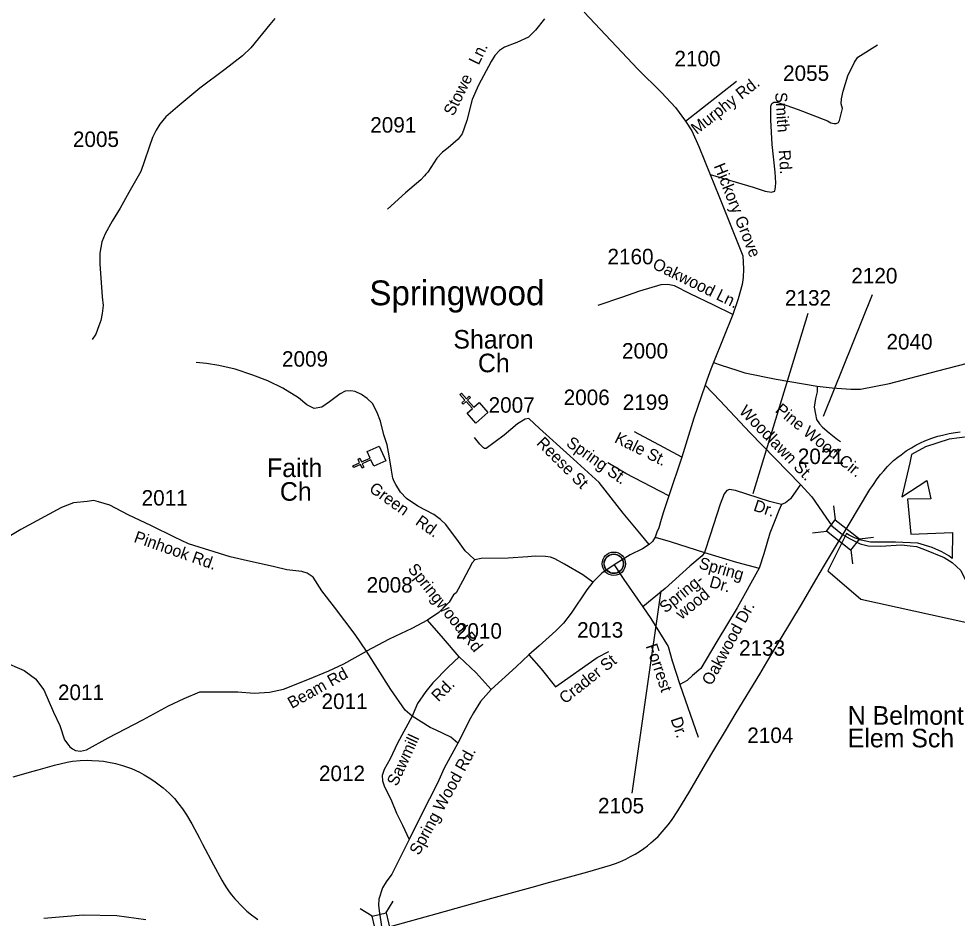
# Model space of a CAD drawing. Extents: x 1364363 to 1407445, y 538563 to 573342.
# Drawn here: x 1379893 to 1387464, y 558110 to 565370 of the extents above; entities that cross this region are included whole.
import ezdxf

# ---------------------------------------------------------------- set-up
doc = ezdxf.new("R2010")
doc.units = 0
for name, color, linetype in [('Exist Boundary Political City Limit New', 7, 'Continuous'), ('Exist Boundary Political City Limit New Hole', 7, 'Continuous'), ('Exist Civil Demographics Community CELL', 7, 'Continuous'), ('Exist Civil Demographics Community Label', 7, 'Continuous'), ('Exist Cultural Church CELL', 7, 'Continuous'), ('Exist Cultural Church Label', 7, 'Continuous'), ('Exist Cultural Educational Facility High Label', 7, 'Continuous'), ('Exist Railroad Mainline', 7, 'Continuous'), ('Exist Road Secondary Structure Standard Bridge CELL', 7, 'Continuous'), ('Exist Road Secondary Type 51 Attributed', 7, 'Continuous'), ('Exist Road Secondary Type 51 Label', 7, 'Continuous'), ('Exist Road Secondary Type 51 Number Label', 7, 'Continuous')]:
    doc.layers.add(name, color=color, linetype=linetype)

msp = doc.modelspace()

# ---------------------------------------------------------------- linework, layer by layer
at = {"layer": 'Exist Boundary Political City Limit New'}
msp.add_lwpolyline([(1380094.6, 558108.9), (1380411.5, 558136.3), (1380683.5, 558130.6), (1380917, 558099.8)], dxfattribs=at)
at = {"layer": 'Exist Boundary Political City Limit New Hole'}
msp.add_lwpolyline([(1387564.9, 561997), (1387398.5, 561975.8), (1387208.6, 561914.4), (1387095.9, 561853.3), (1387082.8, 561784.4), (1387016.4, 561512.2), (1387220.2, 561642.1), (1387252.2, 561495.3), (1387063, 561491.2), (1387091.2, 561209.5), (1387426.9, 561222.6), (1387422.8, 561013.7), (1387397.4, 561035.7), (1387395.4, 561034.4), (1387340.8, 561066.3), (1387262.5, 561102.2), (1387147.6, 561138.1), (1386967.2, 561145.9), (1386888.5, 561144.8), (1386764.6, 561146.2), (1386688.1, 561161), (1386636.6, 561179.1), (1386591.9, 561201.8), (1386571.5, 561215.4), (1386420.9, 560914.8), (1386687.2, 560685.2), (1387541.5, 560497.8)], dxfattribs=at)
at = {"layer": 'Exist Civil Demographics Community CELL'}
msp.add_lwpolyline([(1384616, 560983.3), (1384617, 560988.9), (1384618.8, 560995.5), (1384621.7, 561002.7), (1384624.6, 561008.4), (1384628, 561014.2), (1384631.7, 561019.3), (1384635.7, 561023.7), (1384640.3, 561028.3), (1384645.8, 561032.9), (1384651.3, 561036.5), (1384656.1, 561039.4), (1384661.2, 561041.8), (1384666.6, 561044.1), (1384672.3, 561045.9), (1384676.6, 561047.1), (1384681.5, 561047.8), (1384685.6, 561048.6), (1384692, 561048.8), (1384696.4, 561048.7), (1384702, 561048.5), (1384707, 561047.7), (1384711.9, 561046.7), (1384716.9, 561045.3), (1384722, 561043.4), (1384728.7, 561040.5), (1384734.9, 561037), (1384740, 561033.4), (1384745.2, 561029.4), (1384748.5, 561026.3), (1384752.6, 561021.9), (1384756.5, 561017.2), (1384759.5, 561012.6), (1384762.7, 561007.6), (1384765.1, 561002.4), (1384767.2, 560997.4), (1384768.7, 560992.4), (1384770, 560987.8), (1384771.1, 560981.8), (1384771.7, 560977.1), (1384772, 560971.1), (1384771.8, 560965.3), (1384771.2, 560959.6), (1384770.3, 560954.1), (1384768.7, 560948), (1384766.8, 560942.1), (1384764.5, 560937.1), (1384761.3, 560931.1), (1384758, 560925.7), (1384754.6, 560921), (1384750.4, 560916.3), (1384745.1, 560911.3), (1384740.1, 560907.2), (1384735.1, 560903.8), (1384730.7, 560901.3), (1384723.9, 560898), (1384716.8, 560895.3), (1384710.8, 560893.8), (1384704.2, 560892.5), (1384699.8, 560892.1), (1384695.3, 560891.8), (1384689.7, 560891.8), (1384685.4, 560892.2), (1384679.8, 560893), (1384673.9, 560894.3), (1384669.3, 560895.6), (1384664.1, 560897.4), (1384659.5, 560899.4), (1384655.6, 560901.7), (1384648.8, 560905.7), (1384643.2, 560910), (1384638.3, 560914.5), (1384633.9, 560919.4), (1384630.7, 560923.3), (1384627.7, 560927.5), (1384623.6, 560934.6), (1384621.9, 560938.1), (1384620.2, 560942.2), (1384617.6, 560950.4), (1384616, 560957.4), (1384615.4, 560962.6), (1384615, 560968.9), (1384615, 560973.6), (1384615.5, 560980)], close=True, dxfattribs=at)
for centre, radius in [((1384693.6, 560970.9), 94.3), ((1384693.4, 560971.2), 76.7)]:
    msp.add_circle(centre, radius, dxfattribs=at)
at = {"layer": 'Exist Cultural Church CELL'}
for points in [[(1383510, 562185.3), (1383552.7, 562223.1), (1383502.3, 562280.2), (1383478.3, 562259), (1383467.7, 562271), (1383491.7, 562292.2), (1383452, 562337.3), (1383464, 562347.9), (1383503.8, 562302.7), (1383527.8, 562323.9), (1383538.3, 562311.9), (1383514.3, 562290.8), (1383564.7, 562233.7), (1383608, 562271.7), (1383678.4, 562191.8), (1383580.4, 562105.5)], [(1382757.2, 561757.7), (1382733.8, 561809.6), (1382664.4, 561778.4), (1382677.5, 561749.2), (1382662.9, 561742.7), (1382649.8, 561771.9), (1382594.9, 561747.3), (1382588.4, 561761.9), (1382643.2, 561786.5), (1382630.1, 561815.7), (1382644.7, 561822.3), (1382657.8, 561793.1), (1382727.3, 561824.2), (1382703.8, 561876.9), (1382800.9, 561920.5), (1382854.4, 561801.3)]]:
    msp.add_lwpolyline(points, close=True, dxfattribs=at)
at = {"layer": 'Exist Railroad Mainline'}
for points in [[(1386498.4, 561133.4), (1386583.6, 561275.9), (1386760.3, 561570), (1386782.1, 561603.2), (1386819, 561657.1), (1386845.8, 561692.4), (1386871.4, 561721), (1386901.5, 561754.8), (1386923.8, 561777.3), (1386951.2, 561803.2), (1386983.7, 561830.6), (1387010.7, 561851.3), (1387053.1, 561881.8), (1387094.5, 561907.3), (1387130.4, 561928.9), (1387167.9, 561947.2), (1387202.9, 561963.4), (1387260.1, 561984.4), (1387308.9, 562000.2), (1387344.8, 562009.6), (1387377.9, 562017.3), (1387400.1, 562022.1), (1387415.6, 562024.9), (1387431.3, 562027.6), (1387488.1, 562034.9)], [(1382900.5, 558045.5), (1383267.6, 558147.2), (1383710.8, 558270.8), (1384064.7, 558369.7), (1384147.1, 558392.5), (1384276, 558428.2), (1384482.7, 558485.4), (1384667.5, 558539.3), (1384706.8, 558552.4), (1384740.9, 558565.2), (1384791.7, 558587.7), (1384828.5, 558606.6), (1384849.6, 558618.1), (1384866.2, 558627.9), (1384900.7, 558648.6), (1384934.5, 558671.4), (1384965.9, 558695.2), (1384992.9, 558717.7), (1385011.5, 558734.1), (1385050.7, 558769.4), (1385131.1, 558862.3), (1385158.3, 558899.7), (1385209.4, 558976.2), (1385307.4, 559136.6), (1385434.6, 559353.7), (1385509.9, 559478.5), (1385594.8, 559621), (1385681.9, 559767.1), (1385871.3, 560080.7), (1385927.4, 560176.3), (1386036.2, 560357.8), (1386206.7, 560642.4), (1386323, 560840.3), (1386394, 560958.7), (1386498.4, 561133.4)], [(1379848.2, 559250.7), (1379935, 559274.4), (1379999.3, 559294.7), (1380048.7, 559308.3), (1380181.3, 559344.8), (1380282.3, 559368), (1380327.6, 559376.5), (1380389.1, 559383.2), (1380449.4, 559385.3), (1380482.6, 559384.1), (1380538.6, 559381.1), (1380575.5, 559376.8), (1380604.7, 559372.5), (1380674.4, 559358.6), (1380728.7, 559342.7), (1380802, 559317.4), (1380866.3, 559288.2), (1380905.1, 559268.4), (1380959.3, 559235.6), (1380992.3, 559211.2), (1381057.8, 559161.5), (1381106.2, 559119.6), (1381148.7, 559075.4), (1381183.8, 559031.5), (1381214.2, 558992.3), (1381246.5, 558943), (1381288.5, 558872.6), (1381350.6, 558755.8), (1381376.1, 558707.3), (1381463.9, 558539.9), (1381530.2, 558416.3), (1381550.2, 558384), (1381569.5, 558354.5), (1381590.7, 558322.3), (1381610, 558298.5), (1381636.7, 558265.6), (1381655, 558246.1), (1381679.1, 558219.3), (1381733.6, 558167.6), (1381771.7, 558136.2), (1381799.6, 558114.6), (1381822.7, 558098.5)]]:
    msp.add_lwpolyline(points, dxfattribs=at)
at = {"layer": 'Exist Road Secondary Structure Standard Bridge CELL'}
for p, q in [((1386466.7, 561437.6), (1386480.4, 561325.3)), ((1386296.7, 561220.4), (1386409.1, 561234.1)), ((1386675.3, 561172.1), (1386787.7, 561185.9)), ((1386605.6, 561083), (1386619.3, 560970.7)), ((1382853.8, 558151.8), (1382913.5, 558248)), ((1382743.6, 558126), (1382647.4, 558185.7))]:
    msp.add_line(p, q, dxfattribs=at)
for points in [[(1386480.4, 561325.3), (1386675.6, 561172.6), (1386604.3, 561081.4), (1386409.1, 561234.1)], [(1382799.5, 557884.6), (1382743.1, 558125.9), (1382855.8, 558152.3), (1382912.3, 557910.9)]]:
    msp.add_lwpolyline(points, close=True, dxfattribs=at)
at = {"layer": 'Exist Road Secondary Type 51 Attributed'}
for p, q in [((1385271.8, 564543.9), (1385683.4, 564865.6)), ((1385654.5, 562982.3), (1385496.6, 562596)), ((1385241.4, 561831.6), (1385137.4, 561518.7)), ((1385226.3, 559996.8), (1385374.2, 559570.3))]:
    msp.add_line(p, q, dxfattribs=at)
for points in [[(1381959.8, 565372.2), (1381918.9, 565324.5), (1381763.9, 565134.4), (1381696.6, 565071), (1381555.5, 564961.4), (1381352.8, 564808.6), (1381193.6, 564675.3), (1381078.6, 564578.8), (1381031.8, 564519.3), (1381000.6, 564471.5), (1380971.4, 564412.1), (1380944.1, 564334.1), (1380903.6, 564214.2), (1380878.3, 564137.2), (1380780.7, 563967.5), (1380710.6, 563839.9), (1380646.3, 563735.6), (1380590.7, 563634.2), (1380562, 563567.9), (1380547.4, 563478.2), (1380547.4, 563390.5), (1380567, 563126.4), (1380573.7, 563056.2), (1380565.9, 562991.8), (1380556.1, 562935.3), (1380539.8, 562890), (1380514.7, 562825.1), (1380485.5, 562782.2)], [(1384133.2, 565369.7), (1384061.9, 565277.7), (1384004.4, 565221.1), (1383910.3, 565179.2), (1383811.9, 565141.2), (1383771.9, 565113.9), (1383733.9, 565072), (1383703.7, 565025.2), (1383602.3, 564833.2), (1383549.7, 564717.2), (1383506.8, 564548.5), (1383487.3, 564486.2), (1383469.5, 564441.8), (1383462.1, 564428.9), (1383436.6, 564397.5), (1383356.7, 564329.2), (1383311.8, 564293.2), (1383266, 564243.4), (1383191.9, 564131.3), (1383176.7, 564114.9), (1383167.4, 564101.9), (1383135.8, 564068.6), (1383013.3, 563966), (1382867.7, 563833.5)], [(1384455.3, 565421.9), (1384888.1, 564963.6), (1385079.6, 564774.8), (1385191.1, 564652.9), (1385271.8, 564543.9)], [(1385469.7, 564112.3), (1385816.7, 564009.2), (1385914.5, 563978.4), (1385967, 563971.2), (1385991.4, 563977.2), (1385996.3, 563993.8), (1385998.8, 564013.9), (1386000, 564044.8), (1385995.1, 564131.3), (1385971.9, 564354.2), (1385959.7, 564553.4), (1385959.7, 564663.6), (1385968.2, 564684.9), (1385984.1, 564695.6), (1386008.5, 564695.6), (1386050.1, 564683.8), (1386080.1, 564672), (1386181.2, 564637.7), (1386416.6, 564546.2), (1386444.7, 564529.6), (1386471.6, 564523.7), (1386487.5, 564523.7), (1386507.1, 564532), (1386514.4, 564547.4), (1386537.6, 564645.8), (1386527.8, 564683.8), (1386531.5, 564722.9), (1386544.9, 564785.7), (1386582.8, 564910.2), (1386634.1, 565019.3), (1386661, 565059.6), (1386821.7, 565160.4)], [(1385271.8, 564543.9), (1385323.1, 564464.4), (1385378.8, 564338.3), (1385469.7, 564112.3)], [(1385469.7, 564112.3), (1385541.8, 563939.2), (1385733.6, 563455.5), (1385741, 563351.2), (1385736.1, 563280.1), (1385730, 563224.4), (1385698.2, 563108.2), (1385654.5, 562982.3)], [(1385654.5, 562982.3), (1385500.3, 563058.4), (1385310.9, 563150.8), (1385183.8, 563214.9), (1385130.1, 563225.5), (1385072.6, 563222), (1384901.6, 563171), (1384755.3, 563120.3), (1384565.5, 563055)], [(1386333.6, 562405.1), (1386455.7, 562390.9), (1386606, 562380.2), (1386684.9, 562380.8), (1386918.8, 562425.9), (1387308.2, 562529), (1387714.6, 562633.1), (1387940.9, 562699.4), (1388256.1, 562775.3), (1388329.6, 562787.8), (1388440, 562823.8), (1388532.4, 562880.2), (1388794.4, 563066.5)], [(1383572.6, 561002.7), (1383525.6, 561046.7), (1383495, 561073.9), (1383441.6, 561149.7), (1383338.6, 561287.7), (1383294.6, 561327.7), (1383240.5, 561367.9), (1383113.7, 561435.7), (1383020.7, 561496.7), (1382973.7, 561547.7), (1382934.2, 561610.9), (1382921.2, 561633.5), (1382912, 561662.8), (1382899, 561727.3), (1382881.7, 561840.6), (1382865.7, 561929.6), (1382838.7, 562012.6), (1382810.7, 562122.6), (1382781.7, 562197.6), (1382746.7, 562263.6), (1382702.7, 562305.6), (1382658.7, 562335.6), (1382605.7, 562360.6), (1382570.7, 562366.6), (1382526.7, 562362.6), (1382484.8, 562343.6), (1382400.8, 562278.6), (1382338.1, 562235.5), (1382276.9, 562224.1), (1382217.3, 562253.9), (1382151, 562310.3), (1382022.5, 562386.9), (1381903.6, 562447.6), (1381782.5, 562494), (1381637.7, 562541.1), (1381508.3, 562571.6), (1381408.4, 562587.8), (1381323.5, 562595.3)], [(1385496.6, 562596), (1385475.8, 562541.5), (1385444.7, 562453.2), (1385430.6, 562413.4)], [(1385496.6, 562596), (1385559.4, 562573), (1385686.3, 562532.2), (1385749.5, 562511.8), (1386002.4, 562459.7), (1386333.6, 562405.1)], [(1385430.6, 562413.4), (1385339, 562146.7), (1385241.4, 561831.6)], [(1385430.6, 562413.4), (1385550.4, 562286.6), (1385791.1, 562029.3), (1386200.5, 561609.9)], [(1386333.6, 562405.1), (1386334.8, 562357.7), (1386321.3, 562305.5), (1386309.1, 562234.4), (1386320.1, 562177.5), (1386328.7, 562134.8), (1386353.1, 562099.3), (1386377.5, 562074.4), (1386432.3, 562027.2), (1386498.2, 561973.9), (1386523.3, 561956.9)], [(1384978.2, 561126.3), (1384902.9, 561218.7), (1384767.8, 561379.4), (1384576, 561625.6), (1384339.2, 561842.5), (1384094.7, 562061.9), (1384006.9, 562142.6), (1383979.2, 562138.8), (1383917.2, 562099.9), (1383807.9, 562009.2), (1383664.5, 561901.8), (1383649.7, 561899.9), (1383642.3, 561905.5), (1383613.6, 561936.9), (1383569.1, 561990.7)], [(1385241.4, 561831.6), (1385098.4, 561908.6), (1384859.4, 562036.6)], [(1385137.4, 561518.7), (1384790.9, 561698), (1384646.5, 561786.6)], [(1386046.4, 561449.6), (1385948.7, 561473.3), (1385675, 561563.4), (1385627.3, 561570.5), (1385606.6, 561563.4), (1385583.4, 561536.1), (1385552.8, 561450.8), (1385469.7, 561202.8), (1385425.7, 561062.6)], [(1386200.5, 561609.9), (1386118.5, 561495.8), (1386079.4, 561462.6), (1386046.4, 561449.6)], [(1386200.5, 561609.9), (1386290, 561512.3), (1386403.8, 561346.6), (1386453.4, 561276.8), (1386538.3, 561206.8)], [(1385137.4, 561518.7), (1385093.4, 561388.7), (1385076.4, 561328.7), (1385056.7, 561259.5), (1385040.7, 561226.6), (1385028, 561186.6)], [(1380444, 561474.6), (1380334.7, 561463.8), (1380238.9, 561425), (1380103.7, 561352.8), (1379909.7, 561246.3), (1379724.6, 561138.1)], [(1382698.9, 560265.9), (1382607.6, 560399.8), (1382439.9, 560619.6), (1382338.6, 560751.7), (1382267.5, 560863.1), (1382220.8, 560894.8), (1382177, 560908.3), (1382055.2, 560923), (1381956.6, 560944.9), (1381704.1, 561002.3), (1381597.5, 561027.5), (1381262.2, 561132.7), (1381149, 561184.5), (1380965, 561276.3), (1380776.7, 561366.3), (1380628.2, 561443.5), (1380536.4, 561470.1), (1380497.9, 561481.7), (1380444, 561474.6)], [(1386046.4, 561449.6), (1386024.4, 561401), (1385990.2, 561312.2), (1385952.2, 561216.9), (1385902.7, 561049.8), (1385865.6, 560933.9)], [(1385028, 561186.6), (1385005.4, 561151.1), (1384978.2, 561126.3)], [(1385028, 561186.6), (1385148.5, 561151.1), (1385425.7, 561062.6)], [(1386538.3, 561206.8), (1386601.8, 561172), (1386681, 561131.3), (1386745.3, 561116.7), (1386844.4, 561113.3), (1387015.7, 561122.3), (1387085.6, 561115.6), (1387135.2, 561109.9), (1387199.4, 561086.8), (1387358.3, 561022.6), (1387422.5, 560982), (1387493.5, 560916.6), (1387638.9, 560624.1), (1387746.4, 560415.2), (1387817.7, 560281.7), (1387900.3, 560086.4)], [(1384978.2, 561126.3), (1384924.3, 561091.3), (1384825.1, 561042.9), (1384695.6, 560961.7)], [(1385425.7, 561062.6), (1385406.1, 561036), (1385306.4, 560950.2), (1385108, 560770.6), (1384926.6, 560624.1)], [(1385425.7, 561062.6), (1385682.7, 560982.6), (1385865.6, 560933.9)], [(1383572.6, 561002.7), (1383550.6, 560977.7), (1383473.6, 560829.8), (1383421.6, 560736.8), (1383399.7, 560721.1), (1383364.8, 560659.6), (1383281.7, 560577.8), (1383191.7, 560514.8)], [(1384525.4, 560821.9), (1384444.3, 560881.7), (1384295.5, 560968.5), (1384217.4, 561010.2), (1384182.5, 561022.7), (1384141.5, 561030.7), (1384058.5, 561032.7), (1383998.6, 561025.7), (1383842.6, 561016.7), (1383624.6, 561013.7), (1383572.6, 561002.7)], [(1384695.6, 560961.7), (1384596.4, 560894.1), (1384525.4, 560821.9)], [(1384695.6, 560961.7), (1384773.9, 560843.3), (1384926.6, 560624.1)], [(1385865.6, 560933.9), (1385688.3, 560615.6), (1385524.9, 560344), (1385396.4, 560124.2), (1385328.8, 560067.8), (1385284.9, 560028.4), (1385226.3, 559996.8)], [(1384525.4, 560821.9), (1384475.8, 560759.9), (1384350.7, 560571.1), (1384288.8, 560492.2), (1384226.8, 560430.2), (1384090.4, 560308), (1384009.3, 560234.6)], [(1384926.6, 560624.1), (1384993, 560529.4), (1385132.9, 560303.3), (1385164.3, 560188.4), (1385226.3, 559996.8)], [(1383191.7, 560514.8), (1383062.8, 560447.7), (1382880.5, 560362.1), (1382698.9, 560265.9)], [(1383446.4, 560220.2), (1383318.7, 560366.6), (1383191.7, 560514.8)], [(1380296.7, 559504.8), (1380305.6, 559493.1), (1380325.2, 559476.7), (1380351, 559462.2), (1380390.9, 559459.4), (1380439.1, 559468.4), (1380615.2, 559564.7), (1380894.4, 559711.2), (1381100.8, 559822.9), (1381226, 559882.2), (1381353.3, 559937), (1381519.3, 559938.3), (1381659.4, 559937), (1381792.1, 559926.2), (1381916.7, 559934.3), (1382027.7, 559958.7), (1382225.4, 560037.3), (1382393.3, 560107.8), (1382515.2, 560162), (1382698.9, 560265.9)], [(1383066.9, 559740.5), (1383010.1, 559788.3), (1382895.3, 559956.8), (1382698.9, 560265.9)], [(1383446.4, 560220.2), (1383358.4, 560136.2), (1383234.1, 560010.6), (1383176.7, 559940.2), (1383111.1, 559842.7), (1383066.9, 559740.5)], [(1383703, 559957), (1383583.6, 560091.4), (1383446.4, 560220.2)], [(1384009.3, 560234.6), (1383906.8, 560138.8), (1383703, 559957)], [(1384009.3, 560234.6), (1384107.3, 560123.9), (1384222.3, 559977.6), (1384560.3, 560213.2), (1384653.9, 560263.4)], [(1379761.5, 560184.8), (1379936.1, 560109.5), (1380027.8, 560042.8), (1380094.9, 559953.8), (1380172.6, 559772.9), (1380225, 559665), (1380262.7, 559550.2), (1380296.7, 559504.8)], [(1383703, 559957), (1383618.6, 559859), (1383561.2, 559768.3), (1383537.1, 559725.7), (1383435.1, 559523.7)], [(1383066.9, 559740.5), (1382948.6, 559523), (1382889.7, 559395.6), (1382841.6, 559310.4), (1382825.7, 559261), (1382828.7, 559219.1), (1382839.8, 559177.4), (1382900.8, 559058.5), (1382939.7, 558956.6), (1382987.9, 558860.3), (1383043.1, 558745)], [(1383435.1, 559523.7), (1383377.9, 559570.1), (1383255.7, 559629.3), (1383211.3, 559649.7), (1383066.9, 559740.5)], [(1383435.1, 559523.7), (1383324.2, 559320.4), (1383270.5, 559200), (1383141.5, 558947.3), (1383043.1, 558745)], [(1383043.1, 558745), (1382902.7, 558466.2), (1382857.4, 558403.1), (1382827.2, 558354.8), (1382799, 558262.7), (1382795.6, 558216), (1382800.9, 558170.5), (1382822.4, 558028.1)]]:
    msp.add_lwpolyline(points, dxfattribs=at)
at = {"layer": 'Exist Road Secondary Type 51 Number Label'}
for p, q in [((1386384.6, 562161.5), (1386781, 563142.8)), ((1385819.2, 561537.6), (1386261.1, 562993.3)), ((1385071.8, 560751.3), (1384837.9, 559120.1))]:
    msp.add_line(p, q, dxfattribs=at)

# ---------------------------------------------------------------- texts
at = {"layer": 'Exist Civil Demographics Community Label'}
msp.add_text('Springwood', height=200, rotation=0.00002, dxfattribs=at).set_placement((1382721.3, 563057.3))
at = {"layer": 'Exist Cultural Church Label'}
for s, p in [('Sharon', (1383399.5, 562707.4)), ('Ch', (1383597.5, 562516.4)), ('Faith', (1381895.8, 561670.4)), ('Ch', (1381999.6, 561479.4))]:
    msp.add_text(s, height=150, rotation=0.00002, dxfattribs=at).set_placement(p)
at = {"layer": 'Exist Cultural Educational Facility High Label'}
for s, p in [('N Belmont ', (1386580.9, 559671.7)), ('Elem Sch', (1386580.9, 559488.9))]:
    msp.add_text(s, height=150, dxfattribs=at).set_placement(p)
at = {"layer": 'Exist Road Secondary Type 51 Label'}
for s, rotation, p in [('Stowe   Ln.', 63.77208, (1383400, 564578.2)), ('Murphy Rd.', 38.01039, (1385362.4, 564431.6)), ('Smith    Rd.', 273.51052, (1385995.4, 564774.1)), ('Hickory Grove ', 291.63214, (1385498.4, 564182.1)), ('Oakwood Ln.', 333.97454, (1384997.9, 563358.4)), ('Woodlawn St.', 314.30814, (1385698.2, 562194.9)), ('Pine Wood Cir.', 321.03195, (1385989.2, 562200)), ('Kale St.       ', 333.73954, (1384692.2, 561953.8)), ('Reese St', 314.94559, (1384062.9, 561938.2)), ('Spring St.', 324.87577, (1384302.5, 561927.6)), ('Green   Rd.', 324.4462, (1382712.1, 561559.7)), ('Dr.', 341.7778, (1385814.2, 561400.9)), ('Pinhook Rd.', 340.67783, (1380815.4, 561148.7)), ('Springwood Rd', 308.66021, (1383026.7, 560926.5)), ('Spring', 344.16038, (1385372.7, 560935.4)), ('Spring-', 38.90145, (1385109.3, 560567.9)), (' Dr.', 344.16038, (1385424.4, 560793.9)), ('wood', 38.90145, (1385239.9, 560516.5)), ('Oakwood Dr.', 61.61208, (1385481.3, 559981.2)), ('Forrest', 288.57808, (1384950.2, 560307.6)), ('Crader St', 38.49717, (1384299.7, 559834.6)), ('Beam Rd', 29.18735, (1382095.4, 559798.4)), ('Rd.', 45.29121, (1383279, 559851)), ('Dr.', 288.7627, (1385150.6, 559716.6)), ('Sawmill', 65.21896, (1382944, 559169)), ('Spring Wood Rd.', 61.39422, (1383121.8, 558611.4))]:
    msp.add_text(s, height=95, rotation=rotation, dxfattribs=at).set_placement(p)
at = {"layer": 'Exist Road Secondary Type 51 Number Label'}
for s, p in [('2100', (1385182.8, 564985.8)), ('2055', (1386059.1, 564868.3)), ('2091', (1382728.7, 564450.7)), ('2005', (1380329.7, 564334.8)), ('2160', (1384642.3, 563387.8)), ('2120', (1386609.7, 563233.3)), ('2132', (1386074.5, 563054.7)), ('2040', (1386893.3, 562700.4)), ('2000', (1384759.8, 562627.1)), ('2009', (1382016.5, 562561.7)), ('2006', (1384289, 562251.7)), ('2199', (1384765.8, 562212.4)), ('2007', (1383683.5, 562190)), ('2021', (1386178.1, 561775.7)), ('2011', (1380884.2, 561440.5)), ('2008', (1382699.3, 560737.9)), ('2010', (1383419.1, 560366)), ('2013', (1384397.5, 560374.2)), ('2133', (1385703.8, 560228.6)), ('2011', (1380209, 559870.6)), ('2011', (1382335.7, 559798.6)), ('2104', (1385770.4, 559524.1)), ('2012', (1382314.7, 559216.4)), ('2105', (1384566, 558956.3))]:
    msp.add_text(s, height=125, dxfattribs=at).set_placement(p)

doc.saveas('drawing.dxf')
